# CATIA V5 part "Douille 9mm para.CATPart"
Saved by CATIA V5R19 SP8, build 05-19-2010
Part number: Douille 9mm para
Bounding box of the stored display mesh (mm): x 0 to 18.5, y -4.96 to 4.96, z -4.951 to 4.951
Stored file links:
  C:\Users\Arthur\Desktop\Catia parts\GLOCK\Douille 9mm para.CATPart
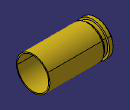
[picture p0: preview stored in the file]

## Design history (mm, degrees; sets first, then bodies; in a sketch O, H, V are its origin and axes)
Set1
  Sketch1 on xy-plane, origin (0, 0, 0), H (1, 0, 0), V (0, 1, 0)
    line L1 (0, 4.96) -> (0, 0)
    point P1 (0, 4.96)
    point P2 (0, 0)
    point P3 (2.17, 4.395)
    line L2 (2.17, 4.395) -> (2.7841, 4.825)
    line L3 (2.7841, 4.825) -> (18.5, 4.825)
    point P5 (18.5, 4.825)
    line L4 (18.5, 4.825) -> (18.5, 0)
    point P6 (18.5, 0)
    construction line L5 (18.5, 0) -> (0, 0)
    line L6 (2.17, 4.395) -> (2.17, 4.395)
    point P7 (2.17, 4.395)
    line L7 (1.27, 4.96) -> (0, 4.96)
    point P9 (0, 4.96)
    line L8 (1.27, 4.96) -> (1.27, 4.395)
    point P10 (1.27, 4.395)
    line L9 (2.17, 4.395) -> (1.27, 4.395)
    distance P3 L5 = 4.395
    distance L3 L5 = 4.825
    angle L2 L5 = 35
    distance L7 L5 = 4.96
    distance L8 L1 = 1.27
    distance P3 P10 = 0.9
    distance V P5 = 18.5
    vertical: L1 V, L4 V, L8 V
    coincidence: P2 H, P6 H, P2 V, P9 P1, P7 P3
    horizontal: L3 H, L5 H, L6 H, L7 H, L9 H
Body1 (main body)
  Shaft1: profile Sketch1, axis Sketch1.H, angle 360
  Sketch2 on face of Shaft1 from Sketch1.L1, origin (0, 0, 0), H (0, -1, 0), V (0, 0, 1)
    circle A1 centre (0, 0) radius 3
    radius A1 = 3
  Pocket1 "Trou amorce": profile Sketch2, direction (1, 0, 0), length 20
  Chamfer1: length 0.3, angle 45, on edge [face of Shaft1 from Sketch1.L1 | face of Shaft1 from Sketch1.L7]
  Chamfer2: length 0.3, angle 45, on edge [face of Shaft1 from Sketch1.L1 | face of Pocket1 from Sketch2.A1]
  Sketch3 on face of Shaft1 from Sketch1.L4, origin (18.5, 0, 0), H (0, 1, 0), V (0, 0, 1)
    circle A1 centre (0, 0) radius 4.515
    radius A1 = 4.515
  Pocket2: profile Sketch3, direction (-1, 0, 0), length 16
